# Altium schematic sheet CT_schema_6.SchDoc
size 300 x 177 mm
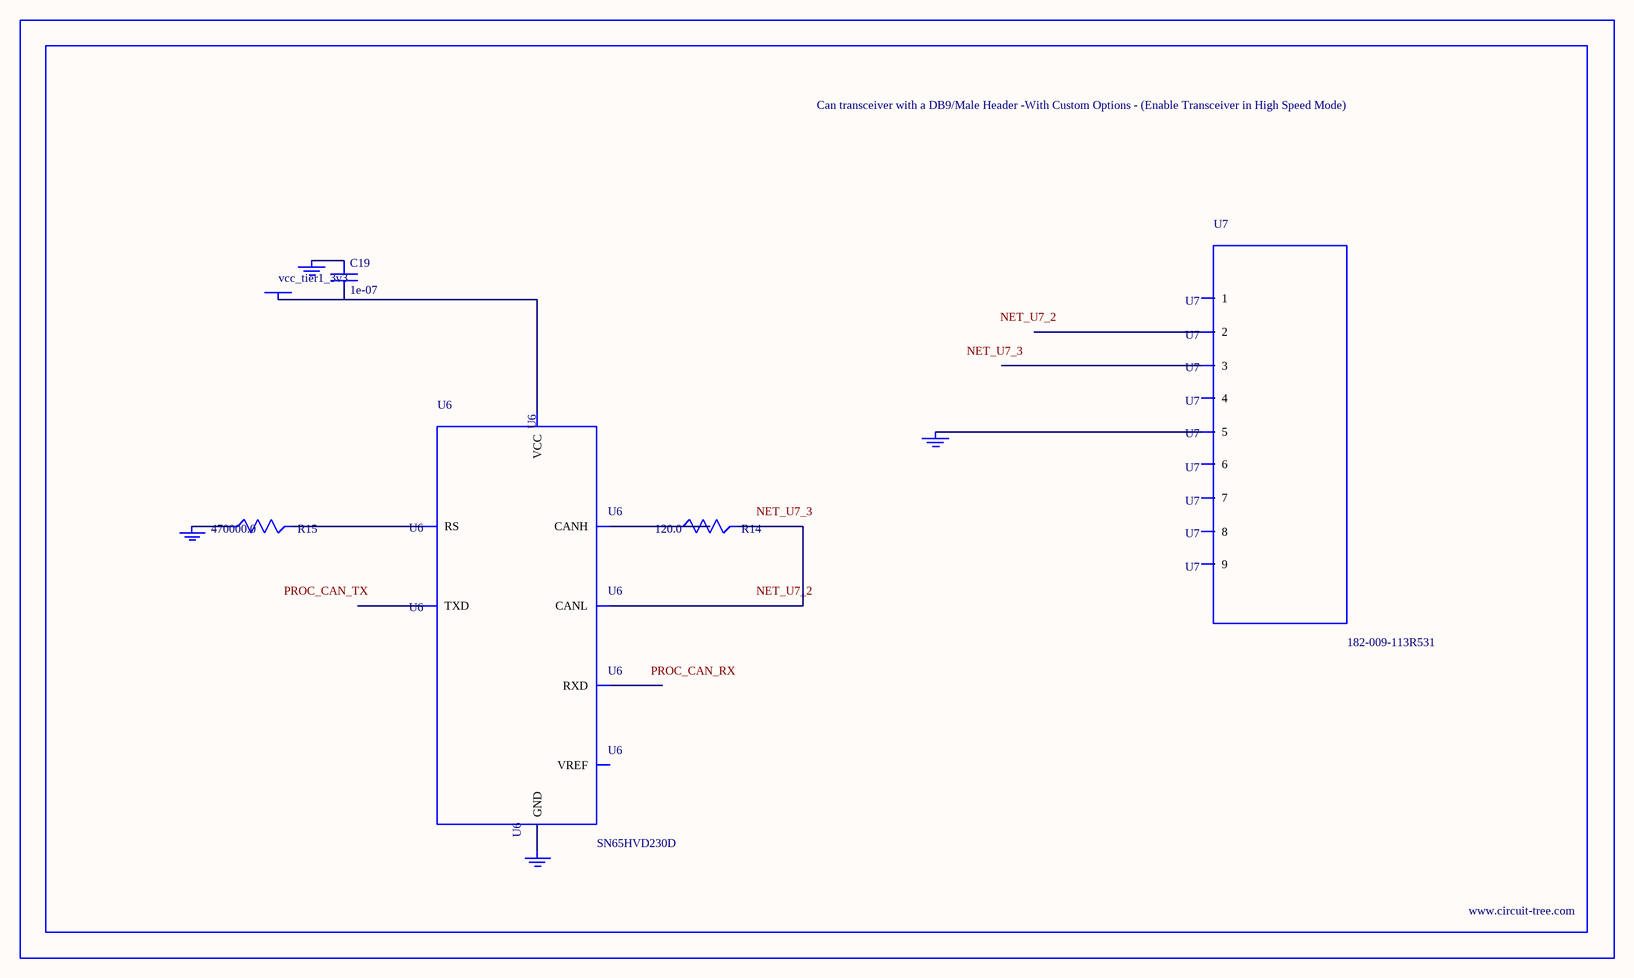
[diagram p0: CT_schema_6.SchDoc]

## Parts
BORDER5  (no value)
C19  1e-07  [C0402]
GND_INSTANCE_5_0  (no value)
GND_INSTANCE_5_1  (no value)
GND_INSTANCE_5_2  (no value)
GND_INSTANCE_5_3  (no value)
POWER_INSTANCE_5_0  vcc_tier1_3v3
R14  120.0  [R0603]
R15  470000.0  [R0603]
U6  SN65HVD230D  [SOIC-8]
U7  182-009-113R531  [182-009-MALE]

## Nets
NetC19_1: C19.1 GND_INSTANCE_5_0.0(GND)
NetC19_2: C19.2 POWER_INSTANCE_5_0.0(PWR) U6.3(VCC)
NetGND_INSTANCE_5_1_0: GND_INSTANCE_5_1.0(GND) R15.1
NetGND_INSTANCE_5_2_0: GND_INSTANCE_5_2.0(GND) U6.2(GND)
NetGND_INSTANCE_5_3_0: GND_INSTANCE_5_3.0(GND) U7.5
NetR14_1: R14.1 U6.7(CANH)
NetR14_2: R14.2 U6.6(CANL)
NetR15_2: R15.2 U6.8(RS)

Not connected (* = marked no-connect by the designer): U6 1(TXD) 4(RXD) 5(VREF); U7 1 2 3 4 6 7 8 9

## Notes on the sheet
- Labels drawn without touching a wire or pin: NET_U7_2, NET_U7_3, PROC_CAN_RX, PROC_CAN_TX

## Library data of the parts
BORDER5 = BORDER_PAGE5
C19 = C0402C104K3RACTU
GND_INSTANCE_5_0-GND_INSTANCE_5_3 = GND
POWER_INSTANCE_5_0 = PWR
R14 = RC0603JR-07120RL
R15 = RC0603JR-07470KL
